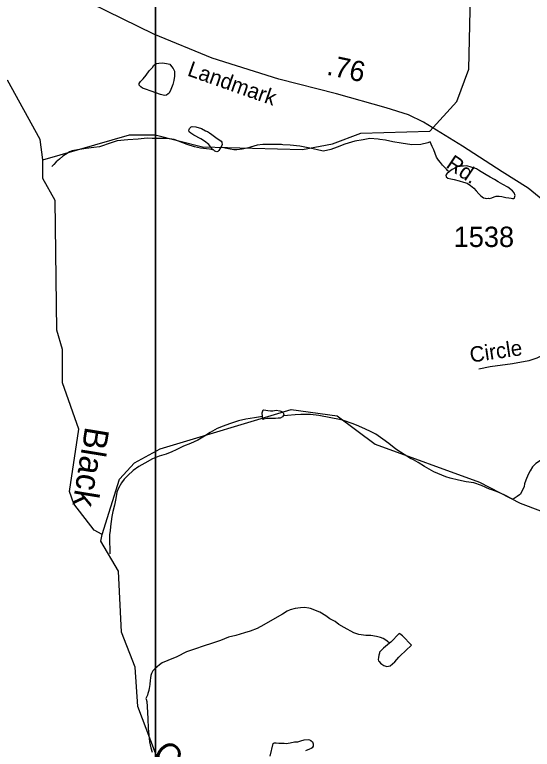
# Model space of a CAD drawing. Extents: x 2082433 to 2279600, y 546599 to 755198.
# Drawn here: x 2102559 to 2105746, y 645891 to 650411 of the extents above; entities that cross this region are included whole.
import ezdxf

# ---------------------------------------------------------------- set-up
doc = ezdxf.new("R2010")
doc.units = 0
for name, color, linetype in [('Exist Hydrographic Creek Single Shore', 7, 'Continuous'), ('Exist Hydrographic Creek Single Shore Label', 7, 'Continuous'), ('Exist Hydrographic Misc Water Feature', 7, 'Continuous'), ('Exist Road Non-System Type 51', 7, 'Continuous'), ('Exist Road Non-System Type 51 Label', 7, 'Continuous'), ('Exist Road Secondary Mileage Hundredths English Label', 7, 'Continuous'), ('Exist Road Secondary Type 51 Attributed', 7, 'Continuous'), ('Exist Road Secondary Type 51 Label', 7, 'Continuous'), ('Exist Road Secondary Type 51 Number Label', 7, 'Continuous'), ('Map Preparation Inset Cut Line', 7, 'Continuous')]:
    doc.layers.add(name, color=color, linetype=linetype)

msp = doc.modelspace()

# ---------------------------------------------------------------- linework, layer by layer
at = {"layer": 'Exist Hydrographic Creek Single Shore'}
for points in [[(2102732.6, 649518.5), (2102715.6, 649643.5), (2102513.6, 650008.5)], [(2103097.6, 647211.4), (2103047.5, 647238.7), (2102922.5, 647402), (2102896.6, 647477.9), (2102953.6, 647860.6), (2102853.6, 648144.8), (2102852.6, 648351.5), (2102818.5, 648470.3), (2102807.7, 649267.6), (2102732.6, 649403.7), (2102732.6, 649518.5)], [(2103811.5, 645274.5), (2103794.5, 645399.5), (2103477.5, 645730.8), (2103317.6, 646153.9), (2103300.6, 646397), (2103216.5, 646611.9), (2103198.5, 646986.3), (2103089.6, 647172.2), (2103097.6, 647211.4)]]:
    msp.add_lwpolyline(points, dxfattribs=at)
at = {"layer": 'Exist Hydrographic Misc Water Feature'}
for points in [[(2102732.6, 649518.5), (2103264.8, 649671.7), (2103423.7, 649671.8), (2103714.6, 649596.9), (2104331.6, 649581.2), (2104514.8, 649616.8), (2104689.7, 649682.1), (2105114.7, 649693.2), (2105280.6, 649876.8), (2105354.7, 650075.4), (2105369.7, 650711.6)], [(2103097.6, 647211.4), (2103204.6, 647553.7), (2103296.5, 647653.5), (2103454.6, 647738.9), (2104261.7, 647981.7), (2104544.7, 647943.1), (2104778.6, 647767.7), (2105420.6, 647535), (2105671.6, 647405.2), (2105938.6, 647304.6), (2106221.6, 647272.7), (2106504.5, 647388.3), (2106720.7, 647406.8), (2106854.6, 647450.1), (2106962.6, 647592.2), (2107052.7, 647866), (2107459.7, 648402.2), (2107892.6, 648583.7), (2108232.8, 648977), (2108688.8, 649778.1), (2108911.7, 650364.1)], [(2103406.8, 650085.9), (2103415, 650099.7), (2103425.1, 650105.9), (2103432.9, 650110), (2103446.8, 650111.9), (2103469, 650113.9), (2103493, 650110.2), (2103513.1, 650106), (2103525.2, 650092.4), (2103535.2, 650080.4), (2103543, 650064.1), (2103543.4, 650032.5), (2103539.3, 650006.3), (2103531.7, 649980.3), (2103519.4, 649950.1), (2103509.4, 649928.1), (2103503.6, 649924.1), (2103493.8, 649916.3), (2103481.5, 649914.1), (2103455.6, 649920), (2103399.5, 649939.9), (2103363.8, 649951.8), (2103345.5, 649957.7), (2103335.5, 649965.8), (2103325.4, 649977.4), (2103325.4, 649987.6), (2103333.8, 649999.7), (2103349.2, 650015.6), (2103367.3, 650037.6), (2103387.4, 650065.8), (2103406.8, 650085.9)], [(2103782.3, 649579.3), (2103778.3, 649579.9), (2103754.4, 649611.2), (2103726.7, 649632.8), (2103704.8, 649647), (2103662.5, 649668.9), (2103642.4, 649680.8), (2103632.6, 649690.8), (2103630.1, 649696.9), (2103632.4, 649704.7), (2103634.2, 649710.4), (2103640.4, 649716.9), (2103644.3, 649720.7), (2103652.3, 649722.7), (2103674, 649720.6), (2103708.3, 649711), (2103734.3, 649696.9), (2103746.2, 649691.1), (2103758.5, 649683.1), (2103772, 649673), (2103788.2, 649661.2), (2103806.3, 649649.1), (2103822.1, 649639.4), (2103830.5, 649633.3), (2103834.6, 649625.4), (2103836.6, 649609.3), (2103828.8, 649595.4)], [(2103782.3, 649579.3), (2103778.3, 649579.9), (2103758.3, 649583), (2103702.3, 649589), (2103666.6, 649596.8), (2103620.5, 649612.8), (2103594.5, 649622.4), (2103540.3, 649642.3), (2103494.6, 649648.1), (2103450.3, 649648.3), (2103404.8, 649649.9), (2103374.6, 649650), (2103318.7, 649645.5), (2103254.5, 649641.4), (2103190.7, 649635.2), (2103134.9, 649616.9), (2103099.1, 649602.9), (2103081, 649597.1), (2103046.8, 649593), (2102999, 649586.8), (2102944.9, 649578.4), (2102912.9, 649572.3), (2102896.9, 649566.6), (2102881.3, 649556.4), (2102855, 649540.1), (2102834.7, 649522.1), (2102815.1, 649506), (2102798.9, 649488.1), (2102787.6, 649476.1)], [(2105116, 649629.3), (2105102.2, 649623.2), (2105059.8, 649611), (2105004.6, 649610.8), (2104938.6, 649620.8), (2104885.9, 649628.4), (2104842, 649638.3), (2104807.8, 649642.3), (2104796.3, 649644.4), (2104745.8, 649648), (2104704.2, 649640.1), (2104652.1, 649631.8), (2104590.6, 649613.5), (2104544.1, 649595.4), (2104504.5, 649581.5), (2104460.6, 649571.1), (2104430.7, 649577.3), (2104396.6, 649585.3), (2104314.6, 649602.6), (2104254.3, 649608.4), (2104210, 649610.7), (2104200.6, 649612.5), (2104136.4, 649612.1), (2104086.6, 649612), (2104050.7, 649608.1), (2104010.3, 649595.9), (2103998.6, 649592), (2103958.6, 649583.9), (2103926.4, 649579.4), (2103908.6, 649579.7), (2103886.3, 649583.5), (2103854.7, 649589.5), (2103828.8, 649595.4)], [(2105236.7, 649445.5), (2105226.3, 649449.9), (2105216.4, 649459.5), (2105204.3, 649471.5), (2105192.6, 649485.5), (2105180.5, 649501.5), (2105168.9, 649515.4), (2105156.6, 649533.5), (2105146.5, 649557.3), (2105138.3, 649579.3), (2105128.5, 649599.4), (2105116, 649629.3)], [(2103828.8, 649595.4), (2103816.5, 649575.4), (2103808.7, 649569.3), (2103802.4, 649567.4), (2103796.9, 649569), (2103790.3, 649571.2), (2103782.3, 649579.3)], [(2105236.7, 649445.5), (2105219.1, 649431.6), (2105212.5, 649423.6), (2105214.8, 649413.5), (2105225, 649403.9), (2105243.1, 649399.9), (2105265, 649395.8), (2105294.8, 649388.1), (2105321, 649380.1), (2105344.6, 649374), (2105364.9, 649360), (2105384.8, 649342.4), (2105400.8, 649326.2), (2105417, 649308.3), (2105429.1, 649296.3), (2105436.9, 649290.3), (2105444.9, 649284.6), (2105455.1, 649282.2), (2105461.3, 649280.5), (2105473.2, 649280.8), (2105479.1, 649280.7), (2105489.1, 649282.8), (2105497.1, 649284.4), (2105510.9, 649290.9), (2105517.2, 649292.7), (2105523, 649294.7), (2105531.2, 649294.7), (2105541, 649294.8), (2105557.2, 649292.8), (2105583.1, 649286.8), (2105601.1, 649282.9), (2105615.3, 649281.1), (2105622.8, 649279.2), (2105631, 649279.2), (2105635.1, 649281), (2105638.8, 649293), (2105639, 649299), (2105633.1, 649314.9), (2105622.8, 649327.1), (2105594.5, 649348.7), (2105564.8, 649366.6), (2105534.7, 649382.6), (2105512.7, 649396.4), (2105486.7, 649410.5), (2105460.6, 649424.6), (2105440.8, 649438.1), (2105430.7, 649444.1), (2105414.5, 649454.3), (2105402.6, 649462.2), (2105368.6, 649472.2), (2105342.7, 649480.2), (2105322.8, 649477.9), (2105298.7, 649477.9), (2105278.6, 649472), (2105252.7, 649457.7), (2105236.7, 649445.5)], [(2104083.5, 647938.6), (2104083.3, 647960.5), (2104087.6, 647978.5), (2104091.3, 647980.4), (2104105.7, 647976.6), (2104117.8, 647974.8), (2104133.5, 647972.8), (2104147.5, 647972.7), (2104167.8, 647976.9), (2104191.8, 647972.9), (2104203.5, 647969.1), (2104211.5, 647961), (2104215.6, 647953), (2104213.3, 647946.9), (2104211.3, 647942.7)], [(2104083.5, 647938.6), (2104035.9, 647930.4), (2103981.8, 647922.3), (2103937.5, 647912), (2103881.9, 647894.1), (2103841.8, 647879.9), (2103806.3, 647863.7), (2103762, 647839.7), (2103728, 647817.6), (2103686.1, 647793.5), (2103640.4, 647773.3), (2103598.2, 647755), (2103552.4, 647733.1), (2103526.6, 647720.8), (2103492.3, 647706.9), (2103448.3, 647694.5), (2103406.4, 647678.5), (2103360.9, 647652.2), (2103322.8, 647630.3), (2103288.5, 647606.4), (2103255.1, 647576.1), (2103233.2, 647553.9), (2103215.5, 647529.8), (2103197.5, 647498), (2103187.2, 647472), (2103181.7, 647433.9), (2103173.3, 647393.8), (2103163.6, 647353.9), (2103157.7, 647323.6), (2103152, 647291.6), (2103147.9, 647261.8), (2103146, 647235.7), (2103142.5, 647211.9), (2103142.5, 647193.7), (2103142.5, 647175.9), (2103142.3, 647154), (2103144.4, 647133.8), (2103144.6, 647119.9), (2103144.6, 647094)], [(2104211.3, 647942.7), (2104207.4, 647936.9), (2104193.2, 647928.9), (2104181.5, 647929.1), (2104163.7, 647926.9), (2104139.9, 647926.8), (2104113.9, 647926.7), (2104091.5, 647922.8), (2104085.6, 647920.4), (2104083.5, 647938.6)], [(2105624.5, 647429.5), (2105576.5, 647455.4), (2105534.5, 647473.1), (2105496.7, 647487), (2105482.6, 647491.1), (2105432.6, 647514.9), (2105384.8, 647530.7), (2105338.4, 647536.5), (2105290.4, 647546.6), (2105240.4, 647558.2), (2105212.3, 647568.1), (2105138.3, 647598), (2105082.3, 647631.6), (2105042.5, 647655.5), (2105014, 647671.6), (2104996.4, 647679.5), (2104956, 647705.5), (2104906, 647737), (2104862.1, 647771.3), (2104825.8, 647799.1), (2104781.9, 647828.8), (2104749.5, 647846.7), (2104719.6, 647860.5), (2104678, 647878.2), (2104641.7, 647892.3), (2104583.6, 647914), (2104569.5, 647918.1), (2104431.5, 647945.5), (2104379.4, 647951.4), (2104319.5, 647951.2), (2104285.5, 647949), (2104239.4, 647945), (2104211.3, 647942.7)], [(2105965.3, 647816.3), (2105939.4, 647788.6), (2105919.8, 647764.4), (2105891.7, 647742.3), (2105855.8, 647720.2), (2105812.1, 647678.1), (2105796.1, 647668), (2105768, 647649.9), (2105746.5, 647628), (2105732.1, 647603.8), (2105720, 647581.7), (2105704.7, 647547.6), (2105698.5, 647523.7), (2105694.6, 647507.7), (2105688.5, 647493.6), (2105679, 647475.6), (2105672.9, 647461.5), (2105666.7, 647455.5), (2105652.8, 647445.5), (2105632.9, 647433.5), (2105624.5, 647429.5)], [(2104865.6, 646543.4), (2104851.4, 646555.3), (2104837.7, 646567.1), (2104827.6, 646573.1), (2104810, 646579), (2104785.8, 646585.1), (2104751.6, 646591.1), (2104719.8, 646591.1), (2104677.8, 646596.6), (2104645.8, 646606.7), (2104587.7, 646640.7), (2104553.7, 646658.4), (2104531.6, 646676.3), (2104499.8, 646694.1), (2104475.2, 646712.1), (2104437, 646734.1), (2104381, 646757.9), (2104369.2, 646759.7), (2104343.3, 646763.6), (2104319.3, 646761.6), (2104285.5, 646757.4), (2104255.1, 646749.4), (2104237.3, 646741.2), (2104207.6, 646721.4), (2104159.4, 646695), (2104091.9, 646656.9), (2104051.5, 646634.6), (2104009.5, 646616.7), (2103973.8, 646606.7), (2103919.7, 646590.5), (2103876, 646580.5), (2103825.8, 646560.1), (2103775.9, 646544.1), (2103718.5, 646525.7), (2103672, 646509.6), (2103616.4, 646489.6), (2103556.5, 646459.3), (2103502.2, 646437.2), (2103466.3, 646423.2), (2103450.7, 646410.9), (2103422.4, 646386.8), (2103408.7, 646373.1), (2103400.9, 646356.8), (2103396.8, 646344.8), (2103394.9, 646330.9), (2103392.9, 646314.6), (2103391.3, 646290.9), (2103388.8, 646274.6), (2103387.2, 646266.8), (2103384.9, 646253), (2103379.2, 646234.8), (2103377.3, 646222.9), (2103366.6, 646202.5), (2103367.3, 646198.8)], [(2104865.6, 646543.4), (2104829.9, 646513.1), (2104803.9, 646489.1), (2104804.3, 646481.3), (2104800.2, 646469), (2104797.7, 646455.1), (2104796.3, 646443.2), (2104798.3, 646435.2), (2104802.4, 646431.4), (2104810, 646421.3), (2104818.4, 646415.1), (2104832, 646405.4), (2104850.2, 646399.4), (2104870.3, 646405.2), (2104884.2, 646417.3), (2104900.2, 646429.5), (2104924, 646457.6), (2104932.2, 646465.6), (2105001.9, 646531.7), (2104945.6, 646589.7), (2104929.8, 646601.4), (2104925.5, 646603.7), (2104873.8, 646549.5), (2104865.6, 646543.4)], [(2103367.3, 646198.8), (2103371.4, 646184.8), (2103375.3, 646154.6), (2103377.9, 646078.8), (2103379.8, 646020.9), (2103383.9, 645979), (2103387.8, 645937), (2103396.2, 645900.8), (2103406, 645872.9)], [(2104131.9, 645849.4), (2104150.2, 645927.4), (2104155.9, 645931.4), (2104168.2, 645931.2), (2104186, 645929.2), (2104202, 645927.6), (2104218, 645927.6), (2104229.9, 645927.5), (2104255.8, 645929.6), (2104282, 645935.8), (2104301.9, 645937.7), (2104319.9, 645943.9), (2104341.7, 645949.9), (2104365.9, 645951.9), (2104373.7, 645949.9), (2104381.9, 645945.8)], [(2104381.9, 645945.8), (2104391.7, 645936.3), (2104395.6, 645923.9), (2104395.8, 645910.1), (2104389.9, 645900), (2104383.7, 645896.1), (2104373.7, 645891.9), (2104348.2, 645882)]]:
    msp.add_lwpolyline(points, dxfattribs=at)
at = {"layer": 'Exist Road Non-System Type 51'}
msp.add_lwpolyline([(2105912, 648385.6), (2105828, 648326.7), (2105772.4, 648297.6), (2105724.8, 648281.7), (2105622.9, 648261.9), (2105486.6, 648244.7), (2105416.4, 648230.1)], dxfattribs=at)
at = {"layer": 'Exist Road Secondary Type 51 Attributed'}
msp.add_lwpolyline([(2106381.6, 648859), (2106282.8, 648914.9), (2106164.9, 649004.9), (2105934.3, 649168.3), (2105720.3, 649343.7), (2105560.4, 649444.3), (2105315.5, 649601.7), (2105075.7, 649748.5), (2104984.2, 649794.7), (2104845.8, 649837.7), (2104540.2, 649924.3), (2104185.3, 650013.7), (2103775.6, 650143.6), (2103415, 650290.7), (2103221.7, 650385.9), (2102937.5, 650525.9), (2102885.5, 650589.3)], dxfattribs=at)
at = {"layer": 'Map Preparation Inset Cut Line'}
for points in [[(2115667.4, 674476.7), (2179108.5, 674476.7), (2179108.5, 645771.4), (2163899.7, 645768.1), (2163899.7, 630228.2), (2103425.3, 630228.2), (2103425.3, 662094.1)], [(2103425.3, 630228.2), (2082433, 644416.2), (2103425.3, 662094.1)]]:
    msp.add_lwpolyline(points, close=True, dxfattribs=at)

# ---------------------------------------------------------------- texts
at = {"layer": 'Exist Hydrographic Creek Single Shore Label'}
for s, rotation, p in [('Black', 260.6935, (2102993.6, 647880.4)), ('Creek', 313.1721, (2103398.9, 645858.8))]:
    msp.add_text(s, height=150, rotation=rotation, dxfattribs=at).set_placement(p)
at = {"layer": 'Exist Road Non-System Type 51 Label'}
msp.add_text('Circle', height=95, rotation=8.3315, dxfattribs=at).set_placement((2105367.5, 648269.7))
at = {"layer": 'Exist Road Secondary Mileage Hundredths English Label'}
msp.add_text('.76', height=125, rotation=348.0078, dxfattribs=at).set_placement((2104473.9, 650042.5))
at = {"layer": 'Exist Road Secondary Type 51 Label'}
for s, rotation, p in [('Landmark', 340.6222, (2103616.2, 650037.6)), ('Rd.', 325.8507, (2105208.6, 649475.4))]:
    msp.add_text(s, height=95, rotation=rotation, dxfattribs=at).set_placement(p)
at = {"layer": 'Exist Road Secondary Type 51 Number Label'}
msp.add_text('1538', height=125, dxfattribs=at).set_placement((2105261.5, 648981.4))

doc.saveas('drawing.dxf')
